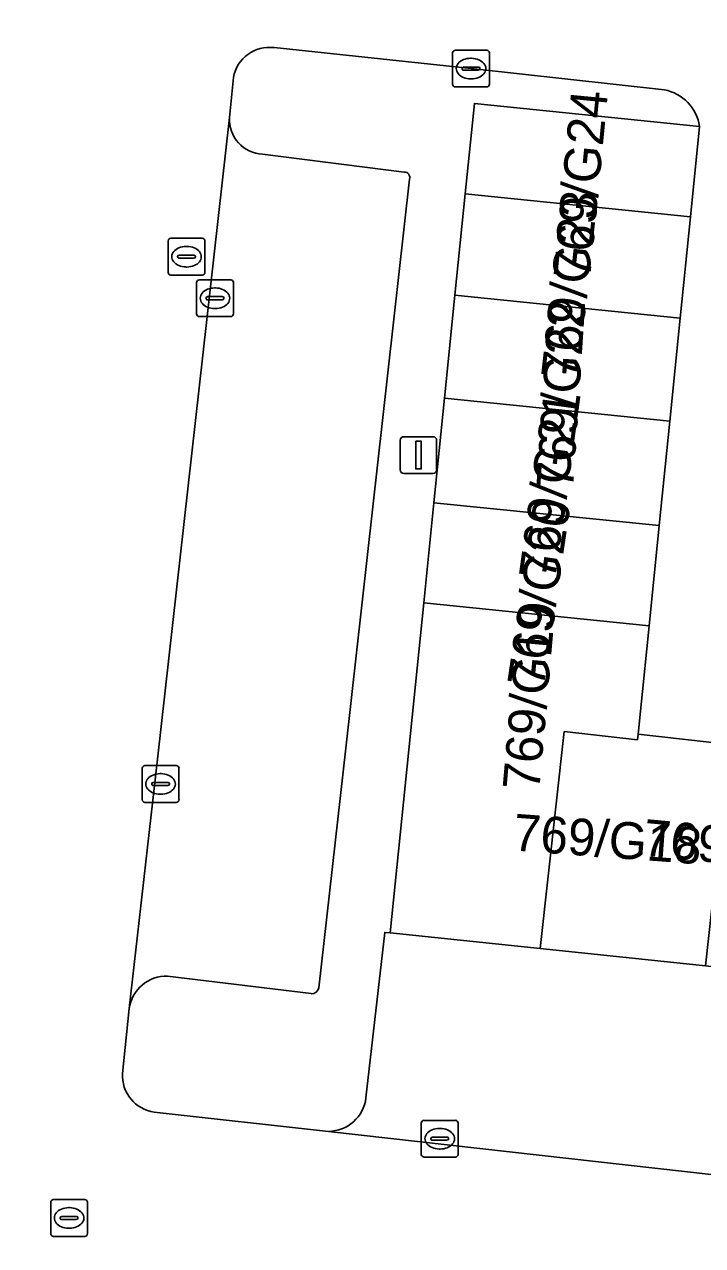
# Model space of a CAD drawing. Extents: x 162026 to 163502, y 387295 to 388169.
# Drawn here: x 162177.41 to 162195.85, y 388114.47 to 388147.67 of the extents above; entities that cross this region are included whole.
import ezdxf

# ---------------------------------------------------------------- set-up
doc = ezdxf.new("R2010")
doc.units = 0
for name, color, linetype in [('IMGEO_Groenvoorziening', 7, 'Continuous'), ('IMGEO_Kolk', 7, 'Continuous'), ('IMGEO_Lichtmast', 7, 'Continuous'), ('IMGEO_Pand', 7, 'Continuous'), ('IMGEO_Pand_nummerreeks', 7, 'Continuous'), ('IMGEO_Parkeervlak_open', 7, 'Continuous'), ('IMGEO_Rijbaan_lokaal_open', 7, 'Continuous'), ('IMGEO_Rioolput', 7, 'Continuous')]:
    doc.layers.add(name, color=color, linetype=linetype)

msp = doc.modelspace()

# ---------------------------------------------------------------- linework, layer by layer
at = {"layer": 'IMGEO_Groenvoorziening'}
for points in [[(162194.817, 388145.891), (162189.556, 388146.468), (162184.201, 388147.037)], [(162183.092, 388146.229), (162182.99, 388145.136)], [(162186.698, 388118.482), (162187.208, 388122.98), (162187.359, 388122.97), (162188.269, 388131.939), (162188.545, 388134.665), (162188.833, 388137.503), (162189.116, 388140.304), (162189.396, 388143.06), (162189.646, 388145.52)], [(162189.646, 388145.52), (162195.771, 388144.897)], [(162183.886, 388144.14), (162187.738, 388143.654)], [(162187.882, 388143.461), (162186.15, 388127.993), (162185.415, 388121.479)], [(162185.209, 388121.316), (162181.304, 388121.794)], [(162180.258, 388120.911), (162180.081, 388119.148)], [(162180.942, 388118.098), (162185.677, 388117.572)]]:
    msp.add_lwpolyline(points, dxfattribs=at)
for centre, radius, start, end in [((162184.078, 388146.041), 1.004, 82.9667, 169.1862), ((162194.581, 388144.709), 1.205, 8.9638, 78.6835), ((162183.928, 388145.079), 0.94, 176.5238, 267.4252), ((162187.741, 388143.506), 0.148, 342.2575, 91.1968), ((162181.279, 388120.762), 1.032, 88.6383, 171.7017), ((162185.224, 388121.509), 0.194, 265.6409, 351.0656), ((162181.07, 388119.081), 0.991, 176.1211, 262.5824), ((162185.663, 388118.615), 1.044, 270.7672, 352.6529)]:
    msp.add_arc(centre, radius, start, end, dxfattribs=at)
at = {"layer": 'IMGEO_Kolk'}
for p, q in [((162189.055, 388146.042), (162189.055, 388146.894)), ((162189.13, 388146.968), (162189.982, 388146.968)), ((162189.543, 388146.748), (162189.568, 388146.748)), ((162190.056, 388146.894), (162190.056, 388146.042)), ((162189.314, 388146.462), (162189.314, 388146.474)), ((162189.752, 388146.425), (162189.354, 388146.425)), ((162189.357, 388146.511), (162189.755, 388146.511)), ((162189.798, 388146.474), (162189.798, 388146.462)), ((162189.566, 388146.188), (162189.541, 388146.188)), ((162189.982, 388145.968), (162189.13, 388145.968)), ((162182.093, 388139.798), (162182.093, 388140.65)), ((162182.168, 388140.724), (162183.02, 388140.724)), ((162182.581, 388140.504), (162182.606, 388140.504)), ((162183.094, 388140.65), (162183.094, 388139.798)), ((162182.352, 388140.218), (162182.352, 388140.23)), ((162182.79, 388140.181), (162182.392, 388140.181)), ((162182.395, 388140.267), (162182.793, 388140.267)), ((162182.836, 388140.23), (162182.836, 388140.218)), ((162182.604, 388139.944), (162182.579, 388139.944)), ((162183.02, 388139.724), (162182.168, 388139.724)), ((162180.688, 388127.518), (162181.54, 388127.518)), ((162180.613, 388126.592), (162180.613, 388127.444)), ((162181.101, 388127.298), (162181.126, 388127.298)), ((162181.614, 388127.444), (162181.614, 388126.592)), ((162180.872, 388127.012), (162180.872, 388127.024)), ((162181.31, 388126.975), (162180.912, 388126.975)), ((162180.915, 388127.061), (162181.313, 388127.061)), ((162181.356, 388127.024), (162181.356, 388127.012)), ((162181.54, 388126.518), (162180.688, 388126.518)), ((162181.124, 388126.738), (162181.099, 388126.738)), ((162188.278, 388117.872), (162189.13, 388117.872)), ((162188.203, 388116.946), (162188.203, 388117.798)), ((162188.691, 388117.652), (162188.716, 388117.652)), ((162189.204, 388117.798), (162189.204, 388116.946)), ((162188.462, 388117.366), (162188.462, 388117.378)), ((162188.9, 388117.329), (162188.502, 388117.329)), ((162188.505, 388117.415), (162188.903, 388117.415)), ((162188.946, 388117.378), (162188.946, 388117.366)), ((162189.13, 388116.872), (162188.278, 388116.872)), ((162188.714, 388117.092), (162188.689, 388117.092))]:
    msp.add_line(p, q, dxfattribs=at)
for points in [[(162189.055, 388146.042), (162189.055, 388146.894)], [(162189.13, 388146.968), (162189.982, 388146.968)], [(162190.056, 388146.894), (162190.056, 388146.042)], [(162189.982, 388145.968), (162189.13, 388145.968)], [(162182.093, 388139.798), (162182.093, 388140.65)], [(162182.168, 388140.724), (162183.02, 388140.724)], [(162183.094, 388140.65), (162183.094, 388139.798)], [(162183.02, 388139.724), (162182.168, 388139.724)], [(162180.688, 388127.518), (162181.54, 388127.518)], [(162180.613, 388126.592), (162180.613, 388127.444)], [(162181.614, 388127.444), (162181.614, 388126.592)], [(162181.54, 388126.518), (162180.688, 388126.518)], [(162188.278, 388117.872), (162189.13, 388117.872)], [(162188.203, 388116.946), (162188.203, 388117.798)], [(162189.204, 388117.798), (162189.204, 388116.946)], [(162189.13, 388116.872), (162188.278, 388116.872)]]:
    msp.add_lwpolyline(points, dxfattribs=at)
for centre, radius, start, end in [((162189.132, 388146.892), 0.0765, 91.552, 178.448), ((162189.132, 388146.892), 0.0765, 91.552, 178.448), ((162189.98, 388146.892), 0.0765, 1.552, 88.448), ((162189.98, 388146.892), 0.0765, 1.552, 88.448), ((162189.354, 388146.471), 0.0403, 85.8775, 175.7526), ((162189.351, 388146.461), 0.0366, 178.938, 274.7102), ((162189.755, 388146.468), 0.043, 264.8664, 352.4533), ((162189.759, 388146.473), 0.0386, 1.7309, 96.639), ((162189.132, 388146.044), 0.0765, 181.552, 268.448), ((162189.132, 388146.044), 0.0765, 181.552, 268.448), ((162189.98, 388146.044), 0.0765, 271.552, 358.448), ((162189.98, 388146.044), 0.0765, 271.552, 358.448), ((162182.17, 388140.648), 0.0765, 91.552, 178.448), ((162182.17, 388140.648), 0.0765, 91.552, 178.448), ((162183.018, 388140.648), 0.0765, 1.552, 88.448), ((162183.018, 388140.648), 0.0765, 1.552, 88.448), ((162182.392, 388140.227), 0.0403, 85.8775, 175.7526), ((162182.389, 388140.217), 0.0366, 178.938, 274.7102), ((162182.793, 388140.224), 0.043, 264.8664, 352.4533), ((162182.797, 388140.229), 0.0386, 1.7309, 96.639), ((162182.17, 388139.8), 0.0765, 181.552, 268.448), ((162182.17, 388139.8), 0.0765, 181.552, 268.448), ((162183.018, 388139.8), 0.0765, 271.552, 358.448), ((162183.018, 388139.8), 0.0765, 271.552, 358.448), ((162180.69, 388127.442), 0.0765, 91.552, 178.448), ((162180.69, 388127.442), 0.0765, 91.552, 178.448), ((162181.538, 388127.442), 0.0765, 1.552, 88.448), ((162181.538, 388127.442), 0.0765, 1.552, 88.448), ((162180.912, 388127.021), 0.0403, 85.8775, 175.7526), ((162180.909, 388127.011), 0.0366, 178.938, 274.7102), ((162181.313, 388127.018), 0.043, 264.8664, 352.4533), ((162181.317, 388127.023), 0.0386, 1.7309, 96.639), ((162180.69, 388126.594), 0.0765, 181.552, 268.448), ((162180.69, 388126.594), 0.0765, 181.552, 268.448), ((162181.538, 388126.594), 0.0765, 271.552, 358.448), ((162181.538, 388126.594), 0.0765, 271.552, 358.448), ((162188.28, 388117.796), 0.0765, 91.552, 178.448), ((162188.28, 388117.796), 0.0765, 91.552, 178.448), ((162189.128, 388117.796), 0.0765, 1.552, 88.448), ((162189.128, 388117.796), 0.0765, 1.552, 88.448), ((162188.502, 388117.375), 0.0403, 85.8775, 175.7526), ((162188.499, 388117.365), 0.0366, 178.938, 274.7102), ((162188.903, 388117.372), 0.043, 264.8664, 352.4533), ((162188.907, 388117.377), 0.0386, 1.7309, 96.639), ((162188.28, 388116.948), 0.0765, 181.552, 268.448), ((162188.28, 388116.948), 0.0765, 181.552, 268.448), ((162189.128, 388116.948), 0.0765, 271.552, 358.448), ((162189.128, 388116.948), 0.0765, 271.552, 358.448)]:
    msp.add_arc(centre, radius, start, end, dxfattribs=at)
for centre, major_axis, ratio, start_param, end_param in [((162189.542, 388146.468), (-0.387, 0.002), 0.722429, 4.712389, 7.853982), ((162189.567, 388146.468), (-0.39, 0.002), 0.717154, 1.570796, 4.712389), ((162182.58, 388140.224), (-0.387, 0.002), 0.722429, 4.712389, 7.853982), ((162182.605, 388140.224), (-0.39, 0.002), 0.717154, 1.570796, 4.712389), ((162181.1, 388127.018), (-0.387, 0.002), 0.722429, 4.712389, 7.853982), ((162181.125, 388127.018), (-0.39, 0.002), 0.717154, 1.570796, 4.712389), ((162188.69, 388117.372), (-0.387, 0.002), 0.722429, 4.712389, 7.853982), ((162188.715, 388117.372), (-0.39, 0.002), 0.717154, 1.570796, 4.712389)]:
    msp.add_ellipse(centre, major_axis=major_axis, ratio=ratio, start_param=start_param, end_param=end_param, dxfattribs=at)
at = {"layer": 'IMGEO_Lichtmast'}
for p, q in [((162187.73, 388136.46), (162188.52, 388136.46)), ((162188.52, 388136.46), (162187.73, 388136.46)), ((162187.63, 388135.56), (162187.63, 388136.36)), ((162187.63, 388136.36), (162187.63, 388135.56)), ((162188.62, 388136.36), (162188.62, 388135.56)), ((162188.62, 388135.56), (162188.62, 388136.36)), ((162188.52, 388135.46), (162187.73, 388135.46)), ((162187.73, 388135.46), (162188.52, 388135.46))]:
    msp.add_line(p, q, dxfattribs=at)
msp.add_lwpolyline([(162188.05, 388136.335), (162188.2, 388136.335), (162188.2, 388135.585), (162188.05, 388135.585), (162188.05, 388136.335)], dxfattribs=at)
for centre, start, end in [((162187.73, 388136.36), 90, 180), ((162187.73, 388136.36), 90, 180), ((162188.52, 388136.36), 0, 90), ((162188.52, 388136.36), 360, 90), ((162187.73, 388135.56), 180, 270), ((162187.73, 388135.56), 180, 270), ((162188.52, 388135.56), 270, 0), ((162188.52, 388135.56), 270, 0)]:
    msp.add_arc(centre, 0.1, start, end, dxfattribs=at)
at = {"layer": 'IMGEO_Pand'}
for points in [[(162195.771, 388144.897), (162189.646, 388145.52), (162189.396, 388143.06), (162195.522, 388142.44)], [(162195.522, 388142.44), (162189.396, 388143.06), (162189.116, 388140.304), (162195.242, 388139.684)], [(162195.242, 388139.684), (162189.116, 388140.304), (162188.833, 388137.503), (162194.958, 388136.882)], [(162194.958, 388136.882), (162188.833, 388137.503), (162188.545, 388134.665), (162194.671, 388134.045)], [(162194.671, 388134.045), (162188.545, 388134.665), (162188.269, 388131.939), (162194.395, 388131.319)], [(162194.395, 388131.319), (162188.269, 388131.939), (162187.359, 388122.97), (162191.435, 388122.543), (162192.091, 388128.442), (162194.078, 388128.221), (162194.096, 388128.37)], [(162194.096, 388128.37), (162194.078, 388128.221), (162192.091, 388128.442), (162191.435, 388122.543), (162195.928, 388122.072), (162196.592, 388128.095)]]:
    msp.add_lwpolyline(points, close=True, dxfattribs=at)
at = {"layer": 'IMGEO_Parkeervlak_open'}
for points in [[(162182.99, 388145.136), (162181.032, 388127.696), (162180.258, 388120.911)], [(162187.738, 388143.654), (162183.886, 388144.14)], [(162186.15, 388127.993), (162187.882, 388143.461)], [(162185.415, 388121.479), (162186.15, 388127.993)], [(162207.254, 388120.886), (162205.572, 388121.062), (162201.271, 388121.512), (162198.599, 388121.792), (162195.928, 388122.072), (162191.435, 388122.543), (162187.359, 388122.97), (162187.208, 388122.98), (162186.698, 388118.482)], [(162181.304, 388121.794), (162185.209, 388121.316)], [(162185.677, 388117.572), (162207.541, 388115.108)]]:
    msp.add_lwpolyline(points, dxfattribs=at)
for centre, radius, start, end in [((162183.928, 388145.079), 0.94, 176.5238, 267.4252), ((162187.741, 388143.506), 0.148, 342.2575, 91.1968), ((162181.279, 388120.762), 1.032, 88.6383, 171.7017), ((162185.224, 388121.509), 0.194, 265.6409, 351.0656), ((162185.663, 388118.615), 1.044, 270.7672, 352.6529)]:
    msp.add_arc(centre, radius, start, end, dxfattribs=at)
at = {"layer": 'IMGEO_Rijbaan_lokaal_open'}
for points in [[(162195.771, 388144.897), (162195.522, 388142.44), (162195.242, 388139.684), (162194.958, 388136.882), (162194.671, 388134.045), (162194.395, 388131.319), (162194.096, 388128.37), (162196.592, 388128.095), (162199.229, 388127.805), (162201.932, 388127.507), (162204.428, 388127.232), (162204.832, 388130.898), (162205.08, 388133.144), (162205.405, 388136.1), (162205.731, 388139.056), (162206.057, 388142.012), (162206.382, 388144.968), (162206.631, 388147.221), (162207.034, 388150.88)], [(162176.665, 388146.91), (162176.16, 388142.394), (162172.827, 388112.903), (162178.468, 388112.268), (162189.728, 388111.001), (162192.161, 388110.716), (162207.999, 388108.964), (162209.13, 388108.814), (162209.74, 388114.919), (162207.541, 388115.108), (162185.677, 388117.572), (162180.942, 388118.098)], [(162184.201, 388147.037), (162189.556, 388146.468), (162194.817, 388145.891)], [(162180.081, 388119.148), (162180.258, 388120.911), (162181.032, 388127.696), (162182.99, 388145.136), (162183.092, 388146.229)]]:
    msp.add_lwpolyline(points, dxfattribs=at)
for centre, radius, start, end in [((162184.078, 388146.041), 1.004, 82.9667, 169.1862), ((162194.581, 388144.709), 1.205, 8.9638, 78.6835), ((162181.07, 388119.081), 0.991, 176.1211, 262.5824)]:
    msp.add_arc(centre, radius, start, end, dxfattribs=at)
at = {"layer": 'IMGEO_Rioolput'}
for p, q in [((162181.319, 388140.927), (162181.319, 388141.779)), ((162181.394, 388141.853), (162182.246, 388141.853)), ((162182.32, 388141.779), (162182.32, 388140.927)), ((162181.807, 388141.633), (162181.832, 388141.633)), ((162181.578, 388141.347), (162181.578, 388141.359)), ((162182.016, 388141.31), (162181.618, 388141.31)), ((162181.621, 388141.396), (162182.019, 388141.396)), ((162181.83, 388141.073), (162181.805, 388141.073)), ((162182.062, 388141.359), (162182.062, 388141.347)), ((162182.246, 388140.853), (162181.394, 388140.853)), ((162178.125, 388114.792), (162178.125, 388115.644)), ((162178.2, 388115.718), (162179.052, 388115.718)), ((162179.126, 388115.644), (162179.126, 388114.792)), ((162178.384, 388115.212), (162178.384, 388115.224)), ((162178.822, 388115.175), (162178.424, 388115.175)), ((162178.427, 388115.261), (162178.825, 388115.261)), ((162178.613, 388115.498), (162178.638, 388115.498)), ((162178.868, 388115.224), (162178.868, 388115.212)), ((162178.636, 388114.938), (162178.611, 388114.938)), ((162179.052, 388114.718), (162178.2, 388114.718))]:
    msp.add_line(p, q, dxfattribs=at)
for points in [[(162181.319, 388140.927), (162181.319, 388141.779)], [(162181.394, 388141.853), (162182.246, 388141.853)], [(162182.32, 388141.779), (162182.32, 388140.927)], [(162182.246, 388140.853), (162181.394, 388140.853)], [(162178.125, 388114.792), (162178.125, 388115.644)], [(162178.2, 388115.718), (162179.052, 388115.718)], [(162179.126, 388115.644), (162179.126, 388114.792)], [(162179.052, 388114.718), (162178.2, 388114.718)]]:
    msp.add_lwpolyline(points, dxfattribs=at)
for centre, radius, start, end in [((162181.396, 388141.777), 0.0765, 91.552, 178.448), ((162181.396, 388141.777), 0.0765, 91.552, 178.448), ((162182.244, 388141.777), 0.0765, 1.552, 88.448), ((162182.244, 388141.777), 0.0765, 1.552, 88.448), ((162181.618, 388141.356), 0.0403, 85.8775, 175.7526), ((162181.615, 388141.346), 0.0366, 178.938, 274.7102), ((162182.019, 388141.353), 0.043, 264.8664, 352.4533), ((162182.023, 388141.358), 0.0386, 1.7309, 96.639), ((162181.396, 388140.929), 0.0765, 181.552, 268.448), ((162181.396, 388140.929), 0.0765, 181.552, 268.448), ((162182.244, 388140.929), 0.0765, 271.552, 358.448), ((162182.244, 388140.929), 0.0765, 271.552, 358.448), ((162178.202, 388115.642), 0.0765, 91.552, 178.448), ((162178.202, 388115.642), 0.0765, 91.552, 178.448), ((162179.05, 388115.642), 0.0765, 1.552, 88.448), ((162179.05, 388115.642), 0.0765, 1.552, 88.448), ((162178.424, 388115.221), 0.0403, 85.8775, 175.7526), ((162178.421, 388115.211), 0.0366, 178.938, 274.7102), ((162178.825, 388115.218), 0.043, 264.8664, 352.4533), ((162178.829, 388115.223), 0.0386, 1.7309, 96.639), ((162178.202, 388114.794), 0.0765, 181.552, 268.448), ((162178.202, 388114.794), 0.0765, 181.552, 268.448), ((162179.05, 388114.794), 0.0765, 271.552, 358.448), ((162179.05, 388114.794), 0.0765, 271.552, 358.448)]:
    msp.add_arc(centre, radius, start, end, dxfattribs=at)
for centre, major_axis, ratio, start_param, end_param in [((162181.806, 388141.353), (-0.387, 0.002), 0.722429, 4.712389, 7.853982), ((162181.831, 388141.353), (-0.39, 0.002), 0.717154, 1.570796, 4.712389), ((162178.612, 388115.218), (-0.387, 0.002), 0.722429, 4.712389, 7.853982), ((162178.637, 388115.218), (-0.39, 0.002), 0.717154, 1.570796, 4.712389)]:
    msp.add_ellipse(centre, major_axis=major_axis, ratio=ratio, start_param=start_param, end_param=end_param, dxfattribs=at)

# ---------------------------------------------------------------- texts
at = {"layer": 'IMGEO_Pand_nummerreeks'}
for s, rotation, p in [('769/G24', 84.5227, (162192.79, 388140.719)), ('769/G23', 83.6576, (162192.451, 388137.991)), ('769/G22', 86.2473, (162192.327, 388135.009)), ('769/G21', 82.1998, (162191.842, 388132.536)), ('769/G20', 81.6341, (162191.526, 388129.611)), ('769/G19', 84.9575, (162191.408, 388126.814)), ('769/G18', 355.7462, (162190.673, 388125.212)), ('769/G17', 354.6442, (162194.198, 388125.07))]:
    msp.add_text(s, height=1, rotation=rotation, dxfattribs=at).set_placement(p)

doc.saveas('drawing.dxf')
